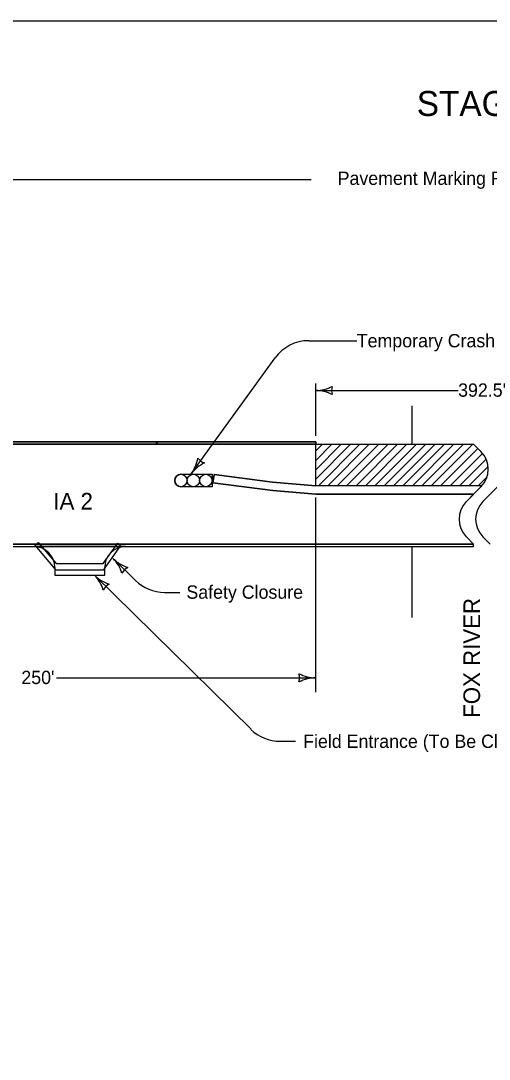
# Model space of a CAD drawing. Extents: x -2134934 to -2119606, y -2139046 to -2137036.
# Drawn here: x -2133929 to -2133366, y -2138285 to -2137036 of the extents above; entities that cross this region are included whole.
import ezdxf

# ---------------------------------------------------------------- set-up
doc = ezdxf.new("R2010")
doc.units = 0
for name, color, linetype in [('Default', 7, 'Continuous'), ('dsnCellElements', 7, 'Continuous'), ('dsnCellsNorthArrow', 7, 'Continuous'), ('dsnStdLabel', 7, 'Continuous'), ('dsnStdLineWork', 7, 'Continuous'), ('Level 2', 7, 'Continuous')]:
    doc.layers.add(name, color=color, linetype=linetype)

msp = doc.modelspace()

# ---------------------------------------------------------------- linework, layer by layer
at = {"layer": 'Default'}
for p, q in [((-2133911.8, -2137666.4), (-2133908.1, -2137663.4)), ((-2133886.7, -2137696.5), (-2133911.8, -2137666.4)), ((-2133908.1, -2137663.4), (-2133886.7, -2137688.4)), ((-2133830.2, -2137688.4), (-2133812.5, -2137664.1)), ((-2133809, -2137666.7), (-2133830.2, -2137696.5)), ((-2133812.5, -2137664.1), (-2133809, -2137666.7)), ((-2133886.7, -2137688.4), (-2133830.2, -2137688.4)), ((-2133830.2, -2137696.5), (-2133886.7, -2137696.5))]:
    msp.add_line(p, q, dxfattribs=at)
msp.add_lwpolyline([(-2134934.4, -2137035.9), (-2131799.4, -2137035.9), (-2131799.4, -2139045.9), (-2134934.4, -2139045.9)], close=True, dxfattribs=at)
at = {"layer": 'dsnCellElements'}
for centre, radius, start, end in [((-2133758.3, -2137555.6), 42.5, 323.701, 351.7735), ((-2133689.8, -2137606), 42.5, 115.6285, 143.701), ((-2133703, -2137552.1), 16.4, 215.9676, 251.4343), ((-2133848.2, -2137712.4), 42.5, 16.6579, 44.7304), ((-2133787.8, -2137652.6), 42.5, 224.7304, 252.8028), ((-2133792.9, -2137707.8), 16.4, 116.997, 152.4637), ((-2133870.6, -2137732.6), 42.5, 16.6579, 44.7304), ((-2133810.2, -2137672.7), 42.5, 224.7304, 252.8028), ((-2133815.3, -2137728), 16.4, 116.997, 152.4637), ((-2133610.1, -2137826), 16.4, 342.2666, 17.7333), ((-2133574.4, -2137783.5), 42.5, 241.9275, 270), ((-2133574.4, -2137868.5), 42.5, 90, 118.0725)]:
    msp.add_arc(centre, radius, start, end, dxfattribs=at)
at = {"layer": 'dsnStdLineWork'}
for p, q in [((-2133766.5, -2137542.2), (-2134239.4, -2137542.2)), ((-2133574.4, -2137542.2), (-2133766.5, -2137542.2)), ((-2133766.5, -2137542.2), (-2133764.3, -2137545.2)), ((-2133764.3, -2137545.2), (-2133766.5, -2137542.2)), ((-2133574.4, -2137545.2), (-2133574.4, -2137542.2)), ((-2133574.4, -2137542.2), (-2133574.4, -2137545.2)), ((-2134239.4, -2137545.2), (-2133764.3, -2137545.2)), ((-2134884.4, -2137665.2), (-2133384.4, -2137665.2)), ((-2134884.4, -2137665.2), (-2133384.4, -2137665.2)), ((-2134884.4, -2137668.2), (-2133384.4, -2137668.2)), ((-2134884.4, -2137668.2), (-2133384.4, -2137668.2)), ((-2133384.4, -2137665.2), (-2134234.4, -2137665.2)), ((-2133384.4, -2137668.2), (-2133384.4, -2137665.2)), ((-2133384.4, -2137668.2), (-2133384.4, -2137665.2))]:
    msp.add_line(p, q, dxfattribs=at)
for points in [[(-2134884.4, -2137542.2), (-2133574.4, -2137542.2)], [(-2134884.9, -2137545.2), (-2133574.9, -2137545.2)], [(-2134884.4, -2137545.2), (-2133574.4, -2137545.2)], [(-2133764.3, -2137545.2), (-2133574.9, -2137545.2), (-2133574.4, -2137545.2)]]:
    msp.add_lwpolyline(points, dxfattribs=at)
at = {"layer": 'Level 2'}
for p, q in [((-2134239.4, -2137227), (-2133580, -2137227)), ((-2133582.7, -2137420.6), (-2133525, -2137420.6)), ((-2133724.1, -2137580.8), (-2133623.3, -2137441.3)), ((-2133574.4, -2137535.2), (-2133574.4, -2137471.9)), ((-2133574.4, -2137480.5), (-2133403.1, -2137480.5)), ((-2133458.6, -2137498.8), (-2133458.6, -2137545.2)), ((-2133574.4, -2137545.2), (-2134884.4, -2137545.2)), ((-2133574.4, -2137553.2), (-2133566.4, -2137545.2)), ((-2133574.4, -2137564.5), (-2133555.1, -2137545.2)), ((-2133574.4, -2137575.8), (-2133543.8, -2137545.2)), ((-2133574.4, -2137595.2), (-2133574.4, -2137545.2)), ((-2133574.4, -2137587.1), (-2133532.5, -2137545.2)), ((-2133574.4, -2137595.2), (-2133574.4, -2137545.2)), ((-2133571.2, -2137595.2), (-2133521.2, -2137545.2)), ((-2133559.9, -2137595.2), (-2133509.9, -2137545.2)), ((-2133548.6, -2137595.2), (-2133498.6, -2137545.2)), ((-2133537.3, -2137595.2), (-2133487.3, -2137545.2)), ((-2133525.9, -2137595.2), (-2133475.9, -2137545.2)), ((-2133514.6, -2137595.2), (-2133464.6, -2137545.2)), ((-2133453.3, -2137545.2), (-2133503.3, -2137595.2)), ((-2133492, -2137595.2), (-2133442, -2137545.2)), ((-2133480.7, -2137595.2), (-2133430.7, -2137545.2)), ((-2133469.4, -2137595.2), (-2133419.4, -2137545.2)), ((-2133458.1, -2137595.2), (-2133408.1, -2137545.2)), ((-2133446.7, -2137595.2), (-2133396.7, -2137545.2)), ((-2133435.4, -2137595.2), (-2133385.4, -2137545.2)), ((-2133424.1, -2137595.2), (-2133379.3, -2137550.3)), ((-2133412.8, -2137595.2), (-2133373.7, -2137556.1)), ((-2133375.7, -2137553.9), (-2133384.4, -2137545.2)), ((-2133401.5, -2137595.2), (-2133369.4, -2137563.1)), ((-2133736.5, -2137581.3), (-2133699, -2137581.3)), ((-2133736.5, -2137581.3), (-2133699, -2137581.3)), ((-2133699, -2137581.3), (-2133699, -2137596.3)), ((-2133699, -2137581.3), (-2133699, -2137596.3)), ((-2133696.7, -2137581.7), (-2133698, -2137591.5)), ((-2133696.7, -2137581.7), (-2133698, -2137591.5)), ((-2133698, -2137591.5), (-2133696.7, -2137581.7)), ((-2133698, -2137591.5), (-2133696.7, -2137581.7)), ((-2133626.2, -2137590.8), (-2133696.7, -2137581.7)), ((-2133626.2, -2137590.8), (-2133696.7, -2137581.7)), ((-2133626.2, -2137590.8), (-2133696.7, -2137581.7)), ((-2133696.7, -2137581.7), (-2133626.2, -2137590.8)), ((-2133390.2, -2137595.2), (-2133367, -2137572)), ((-2133698, -2137591.5), (-2133626, -2137600.8)), ((-2133626, -2137600.8), (-2133698, -2137591.5)), ((-2133626, -2137600.8), (-2133698, -2137591.5)), ((-2133697.9, -2137591.5), (-2133626, -2137600.8)), ((-2133574.1, -2137595.2), (-2133626.2, -2137590.8)), ((-2133574.4, -2137595.1), (-2133626.2, -2137590.8)), ((-2133574.4, -2137595.2), (-2133626.2, -2137590.8)), ((-2133626.2, -2137590.8), (-2133574.4, -2137595.2)), ((-2133378.9, -2137595.2), (-2133368.4, -2137584.7)), ((-2133699, -2137596.3), (-2133736.5, -2137596.3)), ((-2133699, -2137596.3), (-2133736.5, -2137596.3)), ((-2133626, -2137600.8), (-2133574.4, -2137605.2)), ((-2133626, -2137600.8), (-2133574.4, -2137605.2)), ((-2133574.4, -2137605.2), (-2133626, -2137600.8)), ((-2133574.4, -2137605.2), (-2133626, -2137600.8)), ((-2133574.4, -2137595.2), (-2133574.4, -2137595.1)), ((-2133574.2, -2137595.2), (-2133574.4, -2137595.2)), ((-2133374.5, -2137595.2), (-2133574.4, -2137595.2)), ((-2133574.4, -2137605.2), (-2133384.4, -2137605.2)), ((-2133574.4, -2137605.2), (-2133384.4, -2137605.2)), ((-2133384.4, -2137605.2), (-2133574.4, -2137605.2)), ((-2133384.4, -2137605.2), (-2133574.4, -2137605.2)), ((-2133574.1, -2137595.2), (-2133574.2, -2137595.2)), ((-2133374.5, -2137595.2), (-2133574.1, -2137595.2)), ((-2133393.2, -2137613.9), (-2133375.7, -2137596.4)), ((-2133393.2, -2137613.9), (-2133384.4, -2137605.2)), ((-2133384.4, -2137605.2), (-2133375.7, -2137596.4)), ((-2133373.2, -2137613.9), (-2133355.7, -2137596.4)), ((-2133574.4, -2137843.1), (-2133574.4, -2137609.3)), ((-2133384.4, -2137665.2), (-2133393.2, -2137656.4)), ((-2133384.4, -2137665.2), (-2133393.2, -2137656.4)), ((-2133364.4, -2137665.2), (-2133373.2, -2137656.4)), ((-2133373.2, -2137656.4), (-2133364.4, -2137665.2)), ((-2134884.4, -2137665.2), (-2133384.4, -2137665.2)), ((-2133803.2, -2137668.2), (-2133913.2, -2137668.2)), ((-2133458.6, -2137668.2), (-2133458.6, -2137753.6)), ((-2133791.3, -2137708.8), (-2133818, -2137682.5)), ((-2133652.2, -2137887.9), (-2133840.4, -2137702.6)), ((-2133756.2, -2137723.2), (-2133737.8, -2137723.2)), ((-2133886, -2137826), (-2133574.4, -2137826)), ((-2133851.4, -2137826), (-2133801.8, -2137826)), ((-2133617.2, -2137902.3), (-2133598.7, -2137902.3))]:
    msp.add_line(p, q, dxfattribs=at)
for points in [[(-2133574.4, -2137545.2), (-2133384.4, -2137545.2)], [(-2133736.5, -2137581.3), (-2133736.5, -2137581.3)], [(-2133736.5, -2137596.3), (-2133736.5, -2137596.3)], [(-2133574.1, -2137595.2), (-2133574.1, -2137595.2)], [(-2133384.4, -2137605.2), (-2133384.4, -2137605.2)], [(-2133384.4, -2137605.2), (-2133384.4, -2137605.2)], [(-2133364.4, -2137605.2), (-2133364.4, -2137605.2), (-2133373.2, -2137613.9)], [(-2133888.2, -2137693.2), (-2133888.2, -2137702.6), (-2133828.2, -2137702.6), (-2133828.2, -2137693.2)]]:
    msp.add_lwpolyline(points, dxfattribs=at)
for centre in [(-2133736.5, -2137588.8), (-2133736.5, -2137588.8), (-2133721.5, -2137588.8), (-2133721.5, -2137588.8), (-2133706.5, -2137588.8), (-2133706.5, -2137588.8)]:
    msp.add_circle(centre, 7.5, dxfattribs=at)
for centre, radius, start, end in [((-2133582.7, -2137470.6), 50, 90, 144.138), ((-2133574.4, -2137438), 42.5, 270, 298.0725), ((-2133574.4, -2137523), 42.5, 61.9275, 90), ((-2133538.8, -2137480.5), 16.4, 162.2666, 197.7334), ((-2133396.9, -2137575.2), 30, 315, 45), ((-2133736.5, -2137588.8), 7.5, 90.0028, 269.9972), ((-2133396.9, -2137575.2), 30, 315, 318.1884), ((-2133372, -2137635.2), 30, 135, 225), ((-2133372, -2137635.2), 30, 135, 225), ((-2133352, -2137635.2), 30, 135, 225), ((-2133352, -2137635.2), 30, 135, 225), ((-2133913.2, -2137693.2), 25, 0, 90), ((-2133803.2, -2137693.2), 25, 90, 180), ((-2133756.2, -2137673.2), 50, 225.4365, 270), ((-2133617.2, -2137852.3), 50, 225.4365, 270)]:
    msp.add_arc(centre, radius, start, end, dxfattribs=at)

# ---------------------------------------------------------------- texts
at = {"layer": 'dsnCellsNorthArrow'}
msp.add_text('IA 2', height=20, dxfattribs=at).set_placement((-2133889.9, -2137623.6))
msp.add_text('FOX RIVER', height=20, rotation=90, dxfattribs=at).set_placement((-2133376.7, -2137874.1))
at = {"layer": 'dsnStdLabel'}
msp.add_text('STAGE 1', height=30, dxfattribs=at).set_placement((-2133452.8, -2137150.4))
at = {"layer": 'Level 2'}
for s, p in [('Pavement Marking Removal Limits', (-2133548, -2137233.3)), ('Temporary Crash Cushion', (-2133525, -2137428.6)), ("392.5'", (-2133403.1, -2137488)), ('Safety Closure', (-2133729.9, -2137730.9)), ("250'", (-2133928.4, -2137833.5)), ('Field Entrance (To Be Closed)', (-2133589.5, -2137910.3))]:
    msp.add_text(s, height=16, dxfattribs=at).set_placement(p)

doc.saveas('drawing.dxf')
